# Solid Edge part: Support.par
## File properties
Author: there
Template: Iso Metric Part.par
Last saved by: there
Revision: 13
Application: Solid Edge
Precisión: 0.990
Username: there
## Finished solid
Body 1: solid body, 19 faces, 48 edges, 30 vertices.
  Faces by surface: plane 15, cylinder 4
  Edges by curve: line 40, circle 8
Bounding box of the edges (mm): 56.697 x 3.840 x 39.781, from (-28.3486, -3.84, -23.7808) to (28.3486, 0, 16).
Cylindrical faces by radius (mm): R3 x2, R3.2 x1, R16 x1
Planar faces by outward normal: +x 2, +y 2, +z 2, -x 2, -y 1, -z 4, oblique 2
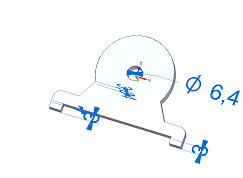
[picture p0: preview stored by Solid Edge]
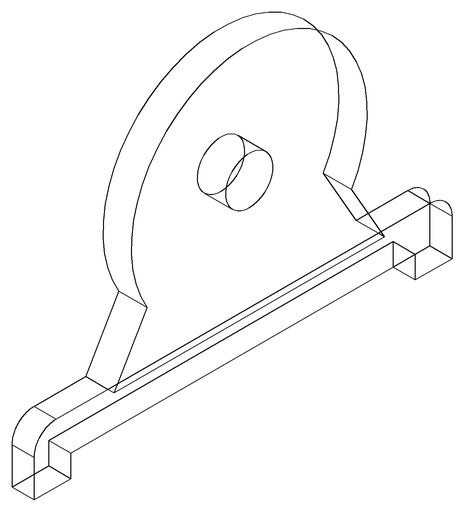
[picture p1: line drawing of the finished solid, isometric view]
